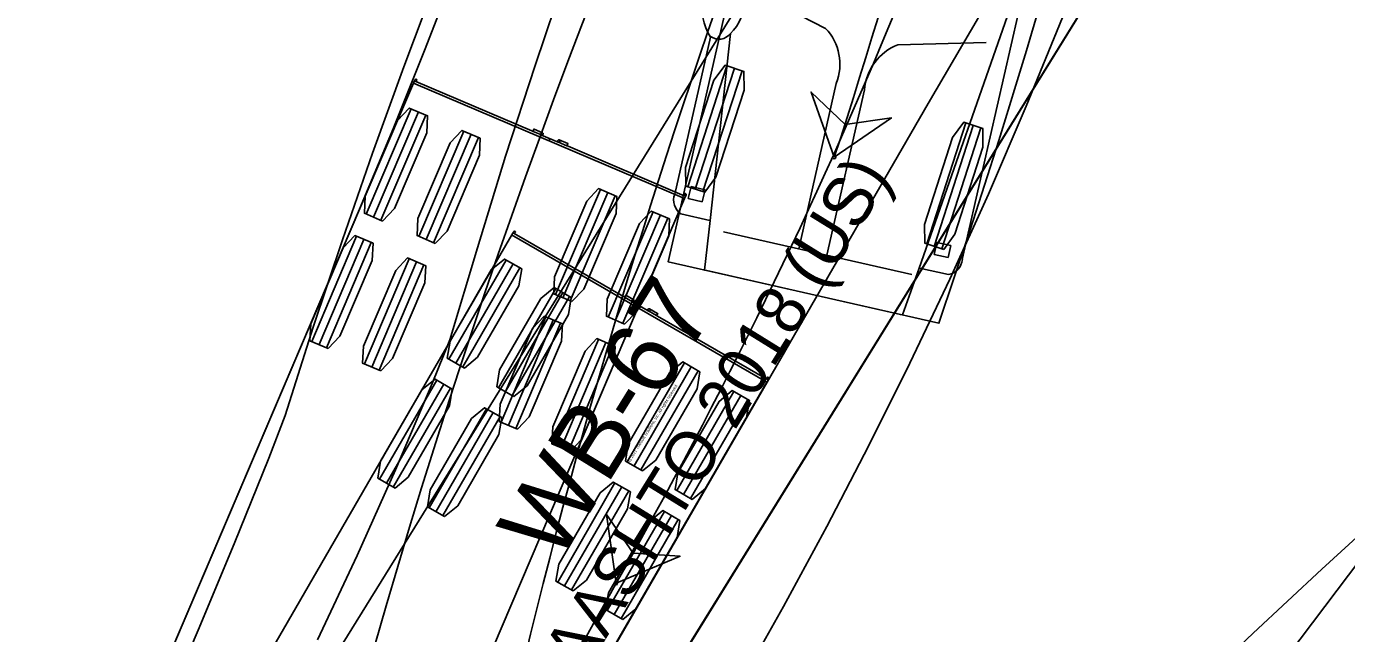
# Model space of a CAD drawing. Extents: x 973688 to 979179, y 703586 to 707602.
# Drawn here: x 973964.39 to 974002.45, y 707271.07 to 707288.59 of the extents above; entities that cross this region are included whole.
import ezdxf

# ---------------------------------------------------------------- set-up
doc = ezdxf.new("R2010")
doc.units = 0
doc.layers.add('0-NPLT', color=7, linetype='Continuous')
doc.layers.add('NO PLOT', color=7, linetype='Continuous')

msp = doc.modelspace()

# ---------------------------------------------------------------- linework, layer by layer
at = {"layer": '0-NPLT'}
for p, q in [((973975.545, 707286.957), (973983.364, 707283.623)), ((973975.545, 707286.957), (973983.364, 707283.623)), ((973974.184, 707283.179), (973975.478, 707286.215)), ((973974.184, 707283.179), (973975.478, 707286.215)), ((973974.395, 707283.089), (973975.689, 707286.125)), ((973974.395, 707283.089), (973975.689, 707286.125)), ((973974.606, 707282.999), (973975.9, 707286.035)), ((973974.606, 707282.999), (973975.9, 707286.035)), ((973975.702, 707282.532), (973976.996, 707285.568)), ((973975.702, 707282.532), (973976.996, 707285.568)), ((973975.913, 707282.442), (973977.207, 707285.478)), ((973975.913, 707282.442), (973977.207, 707285.478)), ((973976.123, 707282.352), (973977.418, 707285.388)), ((973976.123, 707282.352), (973977.418, 707285.388)), ((973978.994, 707285.563), (973979.238, 707285.459)), ((973978.994, 707285.563), (973979.238, 707285.459)), ((973979.483, 707285.355), (973979.455, 707285.29)), ((973979.483, 707285.355), (973979.455, 707285.29)), ((973979.727, 707285.251), (973979.971, 707285.147)), ((973979.727, 707285.251), (973979.971, 707285.147)), ((973979.642, 707280.852), (973980.936, 707283.888)), ((973979.642, 707280.852), (973980.936, 707283.888)), ((973979.853, 707280.762), (973981.147, 707283.798)), ((973979.853, 707280.762), (973981.147, 707283.798)), ((973980.064, 707280.673), (973981.358, 707283.708)), ((973980.064, 707280.673), (973981.358, 707283.708)), ((973981.16, 707280.205), (973982.454, 707283.241)), ((973981.16, 707280.205), (973982.454, 707283.241)), ((973981.371, 707280.115), (973982.665, 707283.151)), ((973981.371, 707280.115), (973982.665, 707283.151)), ((973981.581, 707280.026), (973982.876, 707283.061)), ((973981.581, 707280.026), (973982.876, 707283.061)), ((973972.615, 707279.5), (973973.909, 707282.535)), ((973972.615, 707279.5), (973973.909, 707282.535)), ((973972.826, 707279.41), (973974.12, 707282.445)), ((973972.826, 707279.41), (973974.12, 707282.445)), ((973973.037, 707279.32), (973974.331, 707282.356)), ((973973.037, 707279.32), (973974.331, 707282.356)), ((973974.133, 707278.853), (973975.427, 707281.888)), ((973974.133, 707278.853), (973975.427, 707281.888)), ((973974.344, 707278.763), (973975.638, 707281.798)), ((973974.344, 707278.763), (973975.638, 707281.798)), ((973974.555, 707278.673), (973975.849, 707281.708)), ((973974.555, 707278.673), (973975.849, 707281.708)), ((973978.073, 707277.173), (973979.367, 707280.208)), ((973978.073, 707277.173), (973979.367, 707280.208)), ((973978.284, 707277.083), (973979.578, 707280.119)), ((973978.284, 707277.083), (973979.578, 707280.119)), ((973978.495, 707276.993), (973979.789, 707280.029)), ((973978.495, 707276.993), (973979.789, 707280.029)), ((973979.591, 707276.526), (973980.885, 707279.561)), ((973979.591, 707276.526), (973980.885, 707279.561)), ((973979.802, 707276.436), (973981.096, 707279.471)), ((973979.802, 707276.436), (973981.096, 707279.471)), ((973980.013, 707276.346), (973981.307, 707279.382)), ((973980.013, 707276.346), (973981.307, 707279.382))]:
    msp.add_line(p, q, dxfattribs=at)
for points in [[(973972.781, 707270.893), (973973.929, 707273.329), (973975.031, 707275.795), (973976.085, 707278.289), (973976.595, 707279.547), (973977.39, 707282.203), (973978.204, 707284.846), (973979.052, 707287.468), (973979.932, 707290.07), (973980.845, 707292.652), (973981.791, 707295.214), (973982.752, 707297.716), (973983.732, 707300.168), (973984.739, 707302.594), (973985.773, 707304.997), (973986.835, 707307.381), (973987.941, 707309.778), (973989.392, 707312.801), (973991.62, 707316.554)], [(973972.781, 707270.893), (973973.929, 707273.329), (973975.031, 707275.795), (973976.085, 707278.289), (973976.595, 707279.547), (973977.39, 707282.203), (973978.204, 707284.846), (973979.052, 707287.468), (973979.932, 707290.07), (973980.845, 707292.652), (973981.791, 707295.214), (973982.752, 707297.716), (973983.732, 707300.168), (973984.739, 707302.594), (973985.773, 707304.997), (973986.835, 707307.381), (973987.941, 707309.778), (973989.392, 707312.801), (973991.62, 707316.554)], [(974002.366, 707315.314), (974001.761, 707312.603), (974001.099, 707309.906), (974000.38, 707307.226), (973999.605, 707304.562), (973997.984, 707299.263), (973997.124, 707296.632), (973996.217, 707294.018), (973995.263, 707291.423), (973994.262, 707288.846), (973993.214, 707286.29), (973992.12, 707283.754), (973991.006, 707281.295), (973989.859, 707278.879), (973988.679, 707276.502), (973987.465, 707274.162), (973986.219, 707271.858), (973984.918, 707269.55)], [(974002.366, 707315.314), (974001.761, 707312.603), (974001.099, 707309.906), (974000.38, 707307.226), (973999.605, 707304.562), (973997.984, 707299.263), (973997.124, 707296.632), (973996.217, 707294.018), (973995.263, 707291.423), (973994.262, 707288.846), (973993.214, 707286.29), (973992.12, 707283.754), (973991.006, 707281.295), (973989.859, 707278.879), (973988.679, 707276.502), (973987.465, 707274.162), (973986.219, 707271.858), (973984.918, 707269.55)], [(973967.646, 707226.567), (974034.216, 707314.792)], [(973967.646, 707226.567), (974034.216, 707314.792)], [(973955.568, 707240.095), (973973.993, 707283.317), (973974.96, 707285.637), (973975.886, 707287.944), (973976.785, 707290.277), (973977.659, 707292.644), (973978.499, 707295.02), (973979.305, 707297.406), (973980.075, 707299.801), (973980.809, 707302.204), (973981.507, 707304.614), (973982.167, 707307.031), (973982.79, 707309.455), (973983.374, 707311.884), (973983.92, 707314.318)], [(973955.568, 707240.095), (973973.993, 707283.317), (973974.96, 707285.637), (973975.886, 707287.944), (973976.785, 707290.277), (973977.659, 707292.644), (973978.499, 707295.02), (973979.305, 707297.406), (973980.075, 707299.801), (973980.809, 707302.204), (973981.507, 707304.614), (973982.167, 707307.031), (973982.79, 707309.455), (973983.374, 707311.884), (973983.92, 707314.318)], [(973992.958, 707302.175), (973992.939, 707302.186), (973992.902, 707302.126), (973989.92, 707297.307), (973965.088, 707257.177), (973968.703, 707254.94), (973972.317, 707252.704), (973997.148, 707292.835), (974000.129, 707297.654), (974000.166, 707297.714), (974000.148, 707297.726)], [(973992.958, 707302.175), (973992.939, 707302.186), (973992.902, 707302.126), (973989.92, 707297.307), (973965.088, 707257.177), (973968.703, 707254.94), (973972.317, 707252.704), (973997.148, 707292.835), (974000.129, 707297.654), (974000.166, 707297.714), (974000.148, 707297.726)], [(974003.013, 707302.3), (973983.059, 707270.041)], [(974003.013, 707302.3), (973983.059, 707270.041)], [(973975.594, 707287.013), (973975.574, 707287.021), (973975.546, 707286.956), (973973.323, 707281.743), (973954.816, 707238.332), (973958.725, 707236.666), (973962.635, 707234.999), (973981.142, 707278.41), (973983.364, 707283.624), (973983.391, 707283.689), (973983.371, 707283.697)], [(973975.594, 707287.013), (973975.574, 707287.021), (973975.546, 707286.956), (973973.323, 707281.743), (973954.816, 707238.332), (973958.725, 707236.666), (973962.635, 707234.999), (973981.142, 707278.41), (973983.364, 707283.624), (973983.391, 707283.689), (973983.371, 707283.697)], [(973979.268, 707285.523), (973979.023, 707285.628), (973979.021, 707285.628), (973978.994, 707285.564), (973978.961, 707285.577), (973975.617, 707287.003), (973975.616, 707287.004)], [(973979.268, 707285.523), (973979.023, 707285.628), (973979.021, 707285.628), (973978.994, 707285.564), (973978.961, 707285.577), (973975.617, 707287.003), (973975.616, 707287.004)], [(973979.721, 707285.254), (973979.241, 707285.458)], [(973979.721, 707285.254), (973979.241, 707285.458)], [(973983.349, 707283.707), (973983.348, 707283.707), (973980.004, 707285.133), (973979.971, 707285.147), (973979.999, 707285.211), (973979.998, 707285.212), (973979.752, 707285.317)], [(973983.349, 707283.707), (973983.348, 707283.707), (973980.004, 707285.133), (973979.971, 707285.147), (973979.999, 707285.211), (973979.998, 707285.212), (973979.752, 707285.317)], [(973932.491, 707180.821), (973962.343, 707226.134), (973963.82, 707228.324), (973965.306, 707230.478), (973967.953, 707234.203), (973973.056, 707241.95), (973974.504, 707243.785), (973976.189, 707245.858), (973977.895, 707247.914), (973979.621, 707249.954), (973981.367, 707251.978), (973983.134, 707253.984), (973984.922, 707255.974), (973986.73, 707257.947), (973988.522, 707259.864), (973990.329, 707261.76), (973992.157, 707263.641), (973994.006, 707265.508), (973995.877, 707267.36), (973997.791, 707269.218), (973999.751, 707271.083), (974001.735, 707272.934), (974003.743, 707274.769)], [(973932.491, 707180.821), (973962.343, 707226.134), (973963.82, 707228.324), (973965.306, 707230.478), (973967.953, 707234.203), (973973.056, 707241.95), (973974.504, 707243.785), (973976.189, 707245.858), (973977.895, 707247.914), (973979.621, 707249.954), (973981.367, 707251.978), (973983.134, 707253.984), (973984.922, 707255.974), (973986.73, 707257.947), (973988.522, 707259.864), (973990.329, 707261.76), (973992.157, 707263.641), (973994.006, 707265.508), (973995.877, 707267.36), (973997.791, 707269.218), (973999.751, 707271.083), (974001.735, 707272.934), (974003.743, 707274.769)], [(973981.39, 707272.524), (973983.232, 707273.303), (973981.883, 707273.394), (973981.114, 707274.505), (973981.39, 707272.524)], [(973981.39, 707272.524), (973983.232, 707273.303), (973981.883, 707273.394), (973981.114, 707274.505), (973981.39, 707272.524)], [(973981.39, 707272.524), (973981.225, 707272.234), (973981.061, 707271.944), (973980.899, 707271.653), (973980.738, 707271.361), (973980.578, 707271.068), (973980.42, 707270.775), (973980.263, 707270.481), (973980.107, 707270.186), (973979.953, 707269.891)], [(973981.39, 707272.524), (973981.225, 707272.234), (973981.061, 707271.944), (973980.899, 707271.653), (973980.738, 707271.361), (973980.578, 707271.068), (973980.42, 707270.775), (973980.263, 707270.481), (973980.107, 707270.186), (973979.953, 707269.891)]]:
    msp.add_lwpolyline(points, dxfattribs=at)
for points in [[(973974.658, 707282.977), (973974.132, 707283.201), (973974.154, 707283.694), (973975.086, 707285.88), (973975.426, 707286.237), (973975.952, 707286.013), (973975.929, 707285.52), (973974.998, 707283.335)], [(973974.658, 707282.977), (973974.132, 707283.201), (973974.154, 707283.694), (973975.086, 707285.88), (973975.426, 707286.237), (973975.952, 707286.013), (973975.929, 707285.52), (973974.998, 707283.335)], [(973976.176, 707282.33), (973975.65, 707282.554), (973975.672, 707283.047), (973976.604, 707285.233), (973976.944, 707285.59), (973977.47, 707285.366), (973977.447, 707284.873), (973976.515, 707282.688)], [(973976.176, 707282.33), (973975.65, 707282.554), (973975.672, 707283.047), (973976.604, 707285.233), (973976.944, 707285.59), (973977.47, 707285.366), (973977.447, 707284.873), (973976.515, 707282.688)], [(973980.116, 707280.65), (973979.59, 707280.875), (973979.612, 707281.367), (973980.544, 707283.553), (973980.884, 707283.91), (973981.41, 707283.686), (973981.387, 707283.193), (973980.456, 707281.008)], [(973980.116, 707280.65), (973979.59, 707280.875), (973979.612, 707281.367), (973980.544, 707283.553), (973980.884, 707283.91), (973981.41, 707283.686), (973981.387, 707283.193), (973980.456, 707281.008)], [(973981.634, 707280.003), (973981.108, 707280.228), (973981.13, 707280.72), (973982.062, 707282.906), (973982.402, 707283.263), (973982.928, 707283.039), (973982.905, 707282.546), (973981.973, 707280.361)], [(973981.634, 707280.003), (973981.108, 707280.228), (973981.13, 707280.72), (973982.062, 707282.906), (973982.402, 707283.263), (973982.928, 707283.039), (973982.905, 707282.546), (973981.973, 707280.361)], [(973973.089, 707279.298), (973972.563, 707279.522), (973972.586, 707280.014), (973973.517, 707282.2), (973973.857, 707282.558), (973974.383, 707282.333), (973974.361, 707281.841), (973973.429, 707279.655)], [(973973.089, 707279.298), (973972.563, 707279.522), (973972.586, 707280.014), (973973.517, 707282.2), (973973.857, 707282.558), (973974.383, 707282.333), (973974.361, 707281.841), (973973.429, 707279.655)], [(973974.607, 707278.651), (973974.081, 707278.875), (973974.104, 707279.367), (973975.035, 707281.553), (973975.375, 707281.91), (973975.901, 707281.686), (973975.879, 707281.194), (973974.947, 707279.008)], [(973974.607, 707278.651), (973974.081, 707278.875), (973974.104, 707279.367), (973975.035, 707281.553), (973975.375, 707281.91), (973975.901, 707281.686), (973975.879, 707281.194), (973974.947, 707279.008)], [(973978.547, 707276.971), (973978.021, 707277.195), (973978.044, 707277.688), (973978.976, 707279.873), (973979.315, 707280.231), (973979.841, 707280.006), (973979.819, 707279.514), (973978.887, 707277.328)], [(973978.547, 707276.971), (973978.021, 707277.195), (973978.044, 707277.688), (973978.976, 707279.873), (973979.315, 707280.231), (973979.841, 707280.006), (973979.819, 707279.514), (973978.887, 707277.328)], [(973980.065, 707276.324), (973979.539, 707276.548), (973979.562, 707277.041), (973980.493, 707279.226), (973980.833, 707279.584), (973981.359, 707279.359), (973981.337, 707278.867), (973980.405, 707276.681)], [(973980.065, 707276.324), (973979.539, 707276.548), (973979.562, 707277.041), (973980.493, 707279.226), (973980.833, 707279.584), (973981.359, 707279.359), (973981.337, 707278.867), (973980.405, 707276.681)], [(973981.39, 707272.524), (973983.232, 707273.303), (973981.883, 707273.394), (973981.114, 707274.505)], [(973981.39, 707272.524), (973983.232, 707273.303), (973981.883, 707273.394), (973981.114, 707274.505)]]:
    msp.add_lwpolyline(points, close=True, dxfattribs=at)
for centre, radius in [((973975.618, 707287.04), 0.0266), ((973975.618, 707287.04), 0.0266), ((973983.374, 707283.733), 0.0266), ((973983.374, 707283.733), 0.0266), ((973981.39, 707272.524), 0.0417), ((973981.39, 707272.524), 0.0417), ((973981.39, 707272.524), 0.0417), ((973981.39, 707272.524), 0.0417)]:
    msp.add_circle(centre, radius, dxfattribs=at)
for centre, radius, start, end in [((974170.093, 707224.287), 196.807, 152.83657, 166.91405), ((974170.093, 707224.287), 196.807, 152.83657, 166.91405), ((973854.104, 707344.813), 146.381, 330.40672, 344.86844), ((973854.104, 707344.813), 146.381, 330.40672, 344.86844), ((973976.386, 707288.873), 2.022, 246.9106, 247.5944), ((973976.386, 707288.873), 2.022, 246.9106, 247.5944), ((973979.254, 707285.491), 0.0354, 71.2022, 243.3876), ((973979.254, 707285.491), 0.0354, 71.2022, 243.3876), ((973979.255, 707285.491), 0.0352, 247.885, 66.8854), ((973979.255, 707285.491), 0.0352, 247.885, 66.8854), ((973979.738, 707285.284), 0.0352, 66.9359, 245.9363), ((973979.738, 707285.284), 0.0352, 66.9359, 245.9363), ((973979.739, 707285.284), 0.0353, 250.2468, 68.5965), ((973979.739, 707285.284), 0.0353, 250.2468, 68.5965), ((973983.374, 707283.733), 0.0363, 265.9881, 227.1494), ((973983.374, 707283.733), 0.0363, 265.9881, 227.1494), ((974185.202, 707074.23), 266.14, 130.08412, 142.42531), ((974185.202, 707074.23), 266.14, 130.08412, 142.42531)]:
    msp.add_arc(centre, radius, start, end, dxfattribs=at)
at = {"layer": 'NO PLOT'}
for p, q in [((973993.499, 707291.246), (973990.123, 707281.62)), ((973987.429, 707288.535), (973985.151, 707289.704)), ((973984.69, 707288.384), (973984.097, 707282.989)), ((973989.514, 707288.061), (973992.061, 707288.131)), ((973983.454, 707283.965), (973984.585, 707287.453)), ((973983.672, 707283.895), (973984.803, 707287.382)), ((973983.89, 707283.824), (973985.021, 707287.312)), ((973986.654, 707282.177), (973987.737, 707286.947)), ((973987.467, 707281.993), (973988.551, 707286.763)), ((973990.344, 707282.316), (973991.467, 707285.806)), ((973990.562, 707282.246), (973991.685, 707285.736)), ((973990.78, 707282.175), (973991.903, 707285.666)), ((973983.55, 707283.97), (973983.471, 707283.623)), ((973983.952, 707283.879), (973983.55, 707283.97)), ((973983.874, 707283.532), (973983.952, 707283.879)), ((973983.471, 707283.623), (973983.874, 707283.532)), ((973984.489, 707282.669), (973989.914, 707281.437)), ((973978.378, 707282.58), (973985.737, 707278.326)), ((973990.559, 707282.013), (973990.638, 707282.36)), ((973990.638, 707282.36), (973991.041, 707282.269)), ((973990.962, 707281.922), (973990.559, 707282.013)), ((973991.041, 707282.269), (973990.962, 707281.922)), ((973976.57, 707278.994), (973978.222, 707281.851)), ((973976.769, 707278.88), (973978.42, 707281.737)), ((973976.967, 707278.765), (973978.618, 707281.622)), ((973977.999, 707278.168), (973979.65, 707281.026)), ((973978.197, 707278.054), (973979.849, 707280.911)), ((973978.396, 707277.939), (973980.047, 707280.796)), ((973981.633, 707280.78), (973981.863, 707280.647)), ((973982.093, 707280.514), (973982.058, 707280.453)), ((973982.323, 707280.381), (973982.553, 707280.248)), ((973981.707, 707276.025), (973983.359, 707278.882)), ((973981.906, 707275.91), (973983.557, 707278.767)), ((973982.104, 707275.796), (973983.755, 707278.653)), ((973974.569, 707275.531), (973976.22, 707278.388)), ((973974.767, 707275.416), (973976.418, 707278.273)), ((973974.965, 707275.302), (973976.617, 707278.159)), ((973983.136, 707275.199), (973984.787, 707278.056)), ((973983.334, 707275.085), (973984.986, 707277.942)), ((973983.533, 707274.97), (973985.184, 707277.827)), ((973975.997, 707274.705), (973977.648, 707277.562)), ((973976.195, 707274.591), (973977.847, 707277.448)), ((973976.394, 707274.476), (973978.045, 707277.333)), ((973979.705, 707272.562), (973981.357, 707275.419)), ((973979.904, 707272.447), (973981.555, 707275.304)), ((973980.102, 707272.333), (973981.754, 707275.19)), ((973981.134, 707271.736), (973982.785, 707274.593)), ((973981.332, 707271.621), (973982.984, 707274.479)), ((973981.531, 707271.507), (973983.182, 707274.364))]:
    msp.add_line(p, q, dxfattribs=at)
for points in [[(973999.613, 707315.306), (973999.112, 707312.44), (973998.579, 707309.608), (973998.017, 707306.817), (973997.426, 707304.061), (973996.804, 707301.332), (973996.152, 707298.621), (973995.467, 707295.921), (973994.748, 707293.23), (973993.997, 707290.553), (973993.218, 707287.898), (973992.421, 707285.304), (973991.594, 707282.721), (973990.695, 707280.028), (973982.894, 707281.799), (973986.222, 707296.448), (973986.87, 707298.911), (973987.788, 707302.618), (973985.429, 707349.422)], [(973968.282, 707268.696), (973969.34, 707271.175), (973970.375, 707273.668), (973971.373, 707276.135), (973971.844, 707277.369), (973972.657, 707279.91), (973973.499, 707282.432), (973974.369, 707284.936), (973975.268, 707287.425), (973976.22, 707289.962), (973977.203, 707292.489), (973978.219, 707295.004), (973979.267, 707297.509), (973980.347, 707300.005), (973981.461, 707302.491), (973982.608, 707304.968), (973983.789, 707307.435), (973985.003, 707309.893), (973986.251, 707312.342), (973987.534, 707314.781)], [(974002.651, 707306.576), (974001.249, 707304.396), (973998.482, 707299.973), (973995.756, 707295.483), (973993.06, 707290.942), (973990.385, 707286.366), (973973.357, 707256.874)], [(973993.963, 707289.16), (973992.989, 707288.957), (973992.977, 707288.947), (973991.37, 707281.87)], [(973983.081, 707283.753), (973984.11, 707288.282)], [(973987.68, 707284.814), (973989.327, 707285.95), (973987.988, 707285.766), (973987.009, 707286.698), (973987.68, 707284.814)], [(973990.967, 707281.429), (973990.132, 707281.618), (973990.123, 707281.618), (973989.648, 707280.266), (973989.586, 707280.279), (973986.794, 707280.913), (973984.002, 707281.548), (973983.941, 707281.562), (973984.097, 707282.987), (973984.089, 707282.991), (973983.253, 707283.181)], [(973978.433, 707282.63), (973978.414, 707282.64), (973978.379, 707282.579), (973975.542, 707277.673), (973951.926, 707236.816), (973955.605, 707234.689), (973959.285, 707232.562), (973982.901, 707273.419), (973985.736, 707278.326), (973985.772, 707278.387), (973985.753, 707278.398)], [(973981.9, 707280.707), (973981.669, 707280.84), (973981.668, 707280.84), (973981.633, 707280.78), (973981.602, 707280.798), (973978.454, 707282.617), (973978.454, 707282.618)], [(973982.317, 707280.384), (973981.866, 707280.645)], [(973985.732, 707278.411), (973985.731, 707278.411), (973982.584, 707280.23), (973982.553, 707280.248), (973982.588, 707280.309), (973982.587, 707280.31), (973982.356, 707280.443)]]:
    msp.add_lwpolyline(points, dxfattribs=at)
for points in [[(973983.944, 707283.806), (973983.4, 707283.983), (973983.394, 707284.524), (973984.209, 707287.036), (973984.531, 707287.471), (973985.075, 707287.294), (973985.081, 707286.753), (973984.266, 707284.241)], [(973987.68, 707284.814), (973989.327, 707285.95), (973987.988, 707285.766), (973987.009, 707286.698)], [(973990.834, 707282.158), (973990.29, 707282.333), (973990.283, 707282.875), (973991.091, 707285.388), (973991.412, 707285.824), (973991.957, 707285.649), (973991.964, 707285.107), (973991.155, 707282.594)], [(973977.016, 707278.736), (973976.521, 707279.023), (973976.603, 707279.509), (973977.792, 707281.566), (973978.172, 707281.88), (973978.668, 707281.593), (973978.586, 707281.107), (973977.397, 707279.05)], [(973978.445, 707277.911), (973977.95, 707278.197), (973978.032, 707278.683), (973979.221, 707280.74), (973979.601, 707281.054), (973980.096, 707280.768), (973980.014, 707280.282), (973978.825, 707278.224)], [(973982.153, 707275.767), (973981.658, 707276.053), (973981.74, 707276.54), (973982.929, 707278.597), (973983.309, 707278.91), (973983.805, 707278.624), (973983.723, 707278.138), (973982.534, 707276.081)], [(973975.015, 707275.273), (973974.519, 707275.56), (973974.601, 707276.046), (973975.79, 707278.103), (973976.171, 707278.417), (973976.666, 707278.13), (973976.584, 707277.644), (973975.395, 707275.587)], [(973983.582, 707274.941), (973983.087, 707275.228), (973983.169, 707275.714), (973984.358, 707277.771), (973984.738, 707278.085), (973985.233, 707277.799), (973985.151, 707277.312), (973983.962, 707275.255)], [(973976.443, 707274.448), (973975.948, 707274.734), (973976.03, 707275.22), (973977.219, 707277.277), (973977.599, 707277.591), (973978.095, 707277.305), (973978.013, 707276.818), (973976.824, 707274.761)], [(973980.152, 707272.304), (973979.656, 707272.59), (973979.738, 707273.077), (973980.927, 707275.134), (973981.308, 707275.447), (973981.803, 707275.161), (973981.721, 707274.675), (973980.532, 707272.618)], [(973981.58, 707271.478), (973981.085, 707271.765), (973981.167, 707272.251), (973982.356, 707274.308), (973982.736, 707274.622), (973983.231, 707274.335), (973983.149, 707273.849), (973981.96, 707271.792)]]:
    msp.add_lwpolyline(points, close=True, dxfattribs=at)
for centre, radius in [((973987.68, 707284.814), 0.0417), ((973978.46, 707282.653), 0.0266), ((973985.76, 707278.434), 0.0266)]:
    msp.add_circle(centre, radius, dxfattribs=at)
for centre, radius, start, end in [((974179.595, 707212.24), 213.339, 144.72191, 165.04007), ((973777.621, 707352.668), 220.746, 342.09837, 352.11889), ((973985.397, 707289.109), 1.53, 121.6961, 212.7052), ((973983.441, 707289.543), 1.704, 317.1241, 353.0321), ((973984.355, 707288.647), 0.425, 235.2663, 321.8027), ((973986.323, 707287.496), 1.517, 338.7834, 43.2108), ((973990.063, 707286.647), 1.517, 111.1959, 175.6233), ((973983.534, 707283.577), 0.486, 158.7893, 234.7404), ((973979.445, 707284.38), 2.022, 239.9716, 240.6554), ((973990.886, 707281.908), 0.486, 279.6663, 355.6174), ((973981.882, 707280.676), 0.0354, 64.2632, 236.4486), ((973981.883, 707280.676), 0.0352, 240.946, 59.9464), ((973982.338, 707280.413), 0.0352, 59.9969, 238.9973), ((973982.339, 707280.412), 0.0353, 243.3078, 61.6575), ((973985.76, 707278.434), 0.0363, 259.0491, 220.2104)]:
    msp.add_arc(centre, radius, start, end, dxfattribs=at)

# ---------------------------------------------------------------- texts
at = {"layer": '0-NPLT'}
for s, height, p in [('AASHTO 2018 (US)', 1.41667, (973980.426, 707269.835)), ('AASHTO 2018 (US)', 1.41667, (973980.426, 707269.835)), ('WB-67', 2.125, (973979.706, 707273.047)), ('WB-67', 2.125, (973979.706, 707273.047)), ('(c) 2021 Transoft Solutions, Inc. All rights reserved.', 0.085, (973981.771, 707275.98)), ('(c) 2021 Transoft Solutions, Inc. All rights reserved.', 0.085, (973981.771, 707275.98))]:
    msp.add_text(s, height=height, rotation=58.2526, dxfattribs=at).set_placement(p)

doc.saveas('drawing.dxf')
